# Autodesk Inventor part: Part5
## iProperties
Shininess: 77.0
Length Units: 11269
Angle Units: 11279
Time Units: 11290
Mass Units: 11283
Length Display Precision: 3
Angle Display Precision: 2
Created: 2002-01
Part Number: Part5
Document SubType Name: Modeling
Designer: ***
Density: 0.0
Volumn: 0.0
Area: 0.0
PropertySet Name: Model Information
Control State: 0
Master: False
Checked Out: False
Author: ***
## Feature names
1. Extrusion1
2. Extrusion2
